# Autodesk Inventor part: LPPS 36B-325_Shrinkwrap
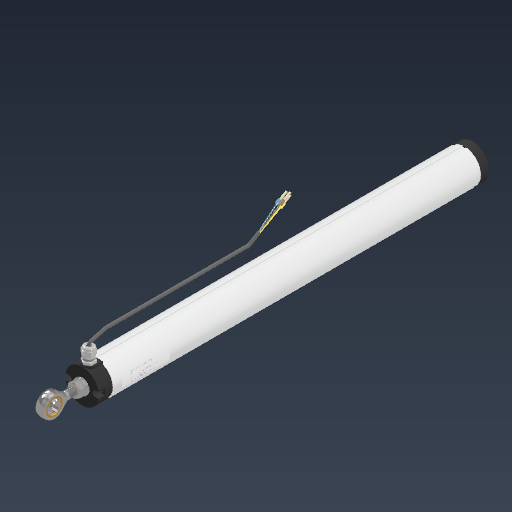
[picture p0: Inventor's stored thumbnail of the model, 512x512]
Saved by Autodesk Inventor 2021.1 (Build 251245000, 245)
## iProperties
Created: 2020-09
Part Number: LPPS 36B-325_Shrinkwrap
Material: Generic
Document SubType Name: Modeling
Designer: J. Nielson
Density: 1 g/cm^3
Appearance: Default
Author: J. Nielson
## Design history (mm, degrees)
derived "LPPS 36B-325.iam"
body "Solid1"
node "LPPS 36B Cable End Cap.iam:1::LPPS-36B PLASTIC CABLE END.ipt"
node "LPPS 36B Cable End Cap.iam:1::LPPS 36B- Cable Gland.ipt:1"
body "Solid2"
node "LPPS 36B Cable End Cap.iam:1::Cable Gland Cap.ipt:1"
body "Solid3"
node "LPPS 36B Cable End Cap.iam:1::Cable.ipt:1"
body "Solid4"
node "LPPS 36B Cable End Cap.iam:1::Cable Gland Seal 1 of 2.ipt:1"
body "Solid5"
node "LPPS 36B Cable End Cap.iam:1::Cable Gland 2 of 2.ipt:1"
body "Solid6"
node "LPPS 36B Cable End Cap.iam:1::#6 Terminal Ring 22 - 18 AWG.i"
body "Solid7"
node "LPPS-36-325 METAL HOUSING.ipt:1"
body "Solid8"
node "MALE Rod Eye SW.ipt:1"
body "Solid9"
node "LPPS-36B PLASTIC STROKE END.ipt:1"
body "Solid10"
node "LPPS 36B-325 Back Stop.ipt:1"
body "Solid11"
node "LPPS 36B-325 Front Stop.ipt:1"
body "Solid12"
node "AS 1427 - M3 x 16.ipt:1"
body "Solid13"
node "AS 1427 - M3 x 16.ipt:2"
body "Solid14"
node "AS 1427 - M3 x 16.ipt:3"
body "Solid15"
node "AS 1427 - M3 x 16.ipt:4"
body "Solid16"
node "AS 1112 - M8  Type 5.ipt:1"
body "Solid17"
node "AS 1968 - 1976 - 8.ipt:1"
body "Solid18"
node "AS 1237 - 8.ipt:1"
body "Solid19"
